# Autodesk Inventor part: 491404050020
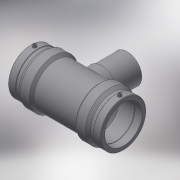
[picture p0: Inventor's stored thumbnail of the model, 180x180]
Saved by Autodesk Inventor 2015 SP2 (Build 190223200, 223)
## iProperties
Created: 2017-06
Part Number: 491404050020
Material: Generic
Description: PLASSON REDUCING TEE 50x20x50
Document SubType Name: Modeling
Designer: KIM
Mass: 229.105 g
Surface Area: 618.349 cm^2
Volume: 229.105 cm^3
Density: 1 g/cm^3
Appearance: Default
Author: KIM
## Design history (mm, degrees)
derived "491404.ipt"
feature "Solid1::491404.ipt"
tag "TaggingFeature1"
body "Solid1"
other parameters: "d0" = 139, "d2" = 68, "d3" = 48, "d4" = 27.8, "d5" = 61.2, "d6" = 47.5, "d8" = 168 deg, "d10" = 19.2, "d11" = 6.4, "d13" = 139, "d14" = 17.6296, "d17" = 45, "d19" = 3.52592, "d20" = 168 deg, "d22" = 63.24, "d23" = 68, "d25" = 135 deg, "d26" = 97.3, "d29" = 52, "d30" = 15, "d31" = 55.6, "d34" = 5 deg, "d35" = 15, "d39" = 5 deg, "d41" = 4, "d42" = 14, "d43" = 0, "d45" = 4, "d46" = 6, "d47" = 0, "d48" = -78, "d51" = 0, "d52" = 16, "d54" = 0, "d55" = 61.2, "d56" = 68, "d57" = 48.65, "d58" = 135 deg, "d59" = 48, "d60" = 48, "d61" = 135 deg, "d62" = 78, "d72" = 63.245, "d73" = 31.6225, "d74" = -78, "d75" = 21, "d77" = 0, "d78" = 16, "d80" = 0, "d82" = 44, "d83" = 0, "d84" = 3, "d85" = 0, "d86" = 16, "d87" = 61.9752, "d88" = 6.4, "d89" = 3, "d90" = 0, "L_" = 139, "L_1" = 48, "D_" = 68, "A_" = 52, "d_2" = 12, "H_" = 78
